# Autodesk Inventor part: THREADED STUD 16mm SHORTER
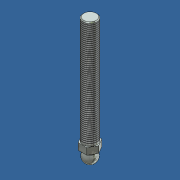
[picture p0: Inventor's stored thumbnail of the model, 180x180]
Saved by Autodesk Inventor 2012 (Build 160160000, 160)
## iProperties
Created: 2007-03
Part Number: THREADED STUD 16mm SHORTER
Document SubType Name: Modeling
Designer: Andy Moles
Material: Steel
Mass: 265.946 g
Surface Area: 89.9795 cm^2
Volume: 33.8784 cm^3
Density: 7.85 g/cm^3
Author: Andy Moles
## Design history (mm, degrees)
sketch "Sketch1"
  geometry: L1 (0, -7.5)-(0, 7.5); A1 r 7.5 centre (0, 0) between (0, -7.5) and (0, 7.5); 1 further point
  constraints: 2 end point, 2 point on circle, 1 centre point, 1 coincident, 1 midpoint, 1 vertical
  dimensions: "d5" = 15 distance of L1.start L1.end
revolve "Revolution1" sketch "Sketch1" stored, may be unused: angle "d1" = 90 deg
sketch "Sketch2"
  geometry: C1 r 6 at (0, 0); 1 further point
  constraints: 1 centre point, 1 coincident
  dimensions: "d2" = 12 diameter of C1
extrude "Extrusion1" join sketch "Sketch2" distance "d3" = 7; taper "d4" = 0 deg
sketch "Sketch3"
  geometry: L1 (-4.907, 8.5)-(4.907, 8.5); L2 (4.907, 8.5)-(9.815, 0); L3 (9.815, 0)-(4.907, -8.5); L4 (4.907, -8.5)-(-4.907, -8.5); L5 (-4.907, -8.5)-(-9.815, 0); L6 (-9.815, 0)-(-4.907, 8.5); C1 r 6 at (0, 0) reference; 1 further point
  constraints: 12 end point, 5 equal length, 1 horizontal, 1 horizontal alignment, 1 midpoint, 1 parallel, 1 vertical alignment
  dimensions: "d6" = 120 deg angle of L6 L5; "d7" = 120 deg angle of L1 L6; "d8" = 17 distance between parallel lines of L4 L1
extrude "Extrusion2" join sketch "Sketch3" distance "d9" = 7.5; taper "d10" = 0 deg
sketch "Sketch4"
  geometry: C1 r 8 at (0, 0); 1 further point
  constraints: 1 centre point, 1 coincident
  dimensions: "d11" = 16 diameter of C1
extrude "Extrusion3" join sketch "Sketch4" distance "d12" = 121.5; taper "d13" = 0 deg
thread "Thread1" dims "d14" = 148, "d15" = 2
chamfer "Chamfer1" distance "d16" = 1; stored, may be unused: second distance "d17" = 2, angle "d18" = 45 deg
body "Solid1"
